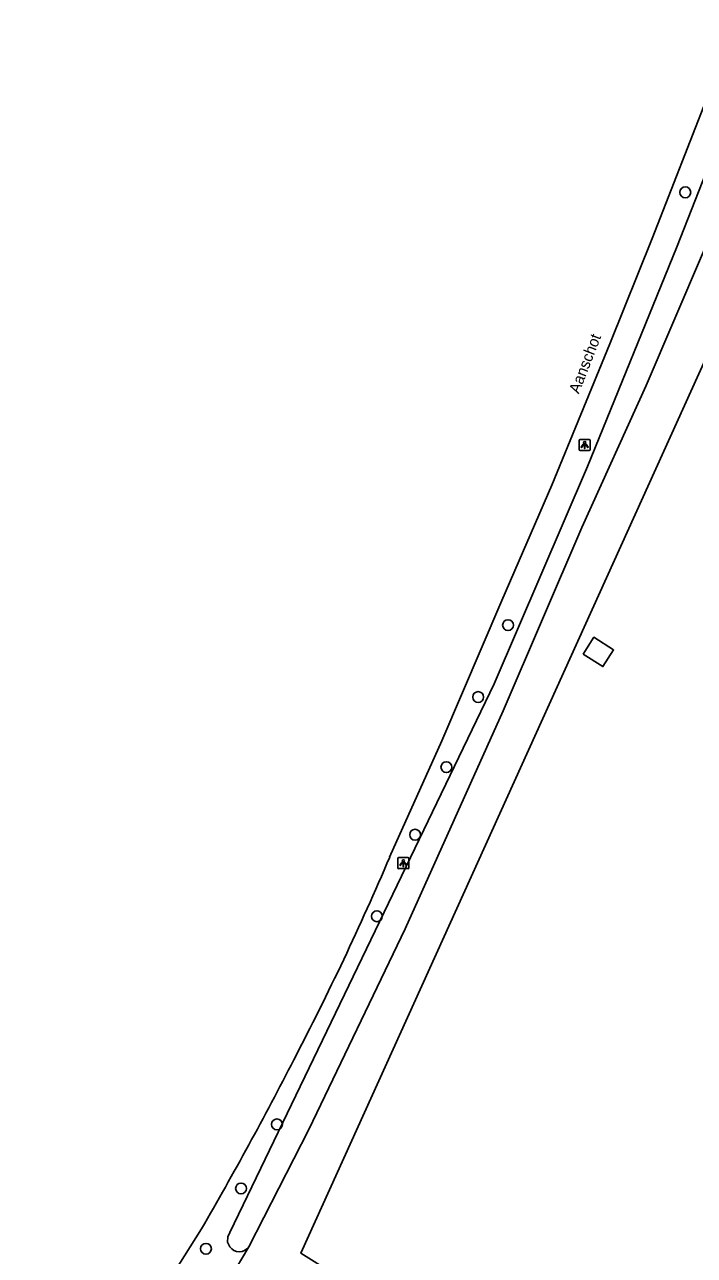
# Model space of a CAD drawing. Extents: x 160457 to 162082, y 388340 to 389736.
# Drawn here: x 160481.5 to 160541.8, y 388848 to 388958.6 of the extents above; entities that cross this region are included whole.
import ezdxf

# ---------------------------------------------------------------- set-up
doc = ezdxf.new("R2010")
doc.units = 0
for name, color, linetype in [('IMGEO_Berm_groen', 7, 'Continuous'), ('IMGEO_Boom', 7, 'Continuous'), ('IMGEO_Groenvoorziening', 7, 'Continuous'), ('IMGEO_Lichtpunt', 7, 'Continuous'), ('IMGEO_Openbare_ruimte_label', 7, 'Continuous'), ('IMGEO_Pand', 7, 'Continuous'), ('IMGEO_Rijbaan_lokaal_gesloten', 7, 'Continuous'), ('IMGEO_Waterloop', 7, 'Continuous')]:
    doc.layers.add(name, color=color, linetype=linetype)

msp = doc.modelspace()

# ---------------------------------------------------------------- linework, layer by layer
at = {"layer": 'IMGEO_Berm_groen'}
msp.add_lwpolyline([(160501.71, 388848.75), (160500, 388845.87), (160499.4, 388844.87)], dxfattribs=at)
at = {"layer": 'IMGEO_Boom'}
for centre in [(160540.95, 388943.5), (160525.02, 388904.61), (160522.33, 388898.15), (160519.47, 388891.85), (160516.66, 388885.78), (160513.22, 388878.45), (160504.24, 388859.75), (160501.01, 388853.99), (160497.85, 388848.57)]:
    msp.add_circle(centre, 0.489, dxfattribs=at)
at = {"layer": 'IMGEO_Groenvoorziening'}
msp.add_lwpolyline([(160548.85, 388958.57), (160549.58, 388958.12), (160554.79, 388954.99), (160591.06, 388933.24), (160604.96, 388924.01), (160605.96, 388923.37), (160626.22, 388910.6), (160664.63, 388832.15), (160676.57, 388807.68), (160619.27, 388780.32), (160613.22, 388781.29), (160506.38, 388848.19), (160550.48, 388945.51), (160551.28, 388947.99), (160553.27, 388951.49), (160549.5, 388954.29), (160548.69, 388954.51), (160548, 388954.61), (160547.57, 388954.6)], dxfattribs=at)
at = {"layer": 'IMGEO_Lichtpunt'}
for p, q in [((160531.41, 388921.2), (160531.41, 388920.39)), ((160531.41, 388921.2), (160531.41, 388920.39)), ((160532.31, 388921.29), (160531.5, 388921.29)), ((160532.31, 388921.29), (160531.5, 388921.29)), ((160532.4, 388920.39), (160532.4, 388921.2)), ((160532.4, 388920.39), (160532.4, 388921.2)), ((160531.5, 388920.3), (160532.31, 388920.3)), ((160531.5, 388920.3), (160532.31, 388920.3)), ((160515.11, 388883.63), (160515.11, 388882.82)), ((160515.11, 388883.63), (160515.11, 388882.82)), ((160516.01, 388883.73), (160515.2, 388883.73)), ((160516.01, 388883.73), (160515.2, 388883.73)), ((160516.1, 388882.82), (160516.1, 388883.63)), ((160516.1, 388882.82), (160516.1, 388883.63)), ((160515.2, 388882.73), (160516.01, 388882.73)), ((160515.2, 388882.73), (160516.01, 388882.73))]:
    msp.add_line(p, q, dxfattribs=at)
for points in [[(160531.78, 388920.86), (160531.82, 388920.83), (160531.63, 388920.57), (160531.59, 388920.6), (160531.78, 388920.86)], [(160531.88, 388920.81), (160531.93, 388920.81), (160531.93, 388920.49), (160531.88, 388920.49), (160531.88, 388920.81)], [(160531.99, 388920.83), (160532.03, 388920.86), (160532.22, 388920.6), (160532.18, 388920.57), (160531.99, 388920.83)], [(160515.48, 388883.29), (160515.52, 388883.27), (160515.33, 388883), (160515.29, 388883.03), (160515.48, 388883.29)], [(160515.58, 388883.25), (160515.63, 388883.25), (160515.63, 388882.92), (160515.58, 388882.92), (160515.58, 388883.25)], [(160515.69, 388883.27), (160515.73, 388883.29), (160515.92, 388883.03), (160515.88, 388883), (160515.69, 388883.27)]]:
    msp.add_lwpolyline(points, dxfattribs=at)
for centre in [(160531.91, 388921), (160515.61, 388883.43)]:
    msp.add_circle(centre, 0.0994, dxfattribs=at)
for centre, start, end in [((160531.5, 388921.2), 90, 180), ((160531.5, 388921.2), 90, 180), ((160531.5, 388920.39), 180, 270), ((160531.5, 388920.39), 180, 270), ((160532.31, 388921.2), 0, 90), ((160532.31, 388921.2), 0, 90), ((160532.31, 388920.39), 270, 0), ((160532.31, 388920.39), 270, 360), ((160515.2, 388883.63), 90, 180), ((160515.2, 388883.63), 90, 180), ((160515.2, 388882.82), 180, 270), ((160515.2, 388882.82), 180, 270), ((160516.01, 388883.63), 0, 90), ((160516.01, 388883.63), 0, 90), ((160516.01, 388882.82), 270, 0), ((160516.01, 388882.82), 270, 360)]:
    msp.add_arc(centre, 0.0946, start, end, dxfattribs=at)
at = {"layer": 'IMGEO_Pand'}
msp.add_lwpolyline([(160531.77, 388902), (160532.73, 388903.52), (160534.5, 388902.39), (160533.54, 388900.88), (160531.77, 388902)], dxfattribs=at)
at = {"layer": 'IMGEO_Rijbaan_lokaal_gesloten'}
for points in [[(160514.37, 388883.76), (160519.07, 388894.2), (160524.47, 388906.81), (160528.94, 388917.2), (160534.18, 388929.89), (160537.97, 388939.34), (160543.09, 388952.48)], [(160481.55, 388825.94), (160489.45, 388837.67), (160494.04, 388844.95), (160497.44, 388850.35)]]:
    msp.add_lwpolyline(points, dxfattribs=at)
for centre, radius, start, end in [((160273.81, 388986.49), 261.58, 332.4624, 336.8755), ((160219.73, 389012), 321.33, 329.7984, 332.8878)]:
    msp.add_arc(centre, radius, start, end, dxfattribs=at)
at = {"layer": 'IMGEO_Waterloop'}
for points in [[(160500, 388848.74), (160499.8, 388849.17), (160499.81, 388849.63), (160500, 388850.03), (160523.77, 388899.32), (160532.16, 388918.87), (160540.17, 388938.52), (160546.23, 388953.92), (160547.21, 388953.47)], [(160547.21, 388953.47), (160548.69, 388952.79), (160545.08, 388943.98), (160537.43, 388926.15), (160531.65, 388913.37), (160524.59, 388896.9), (160515.78, 388877.31), (160507.09, 388859.3), (160501.71, 388848.75)]]:
    msp.add_lwpolyline(points, dxfattribs=at)
msp.add_arc((160500.85, 388849.38), 1.07, 216.9503, 323.5862, dxfattribs=at)

# ---------------------------------------------------------------- texts
at = {"layer": 'IMGEO_Openbare_ruimte_label'}
msp.add_text('Aanschot', height=1, rotation=68.7198, dxfattribs=at).set_placement((160531.38, 388925.34))

doc.saveas('drawing.dxf')
